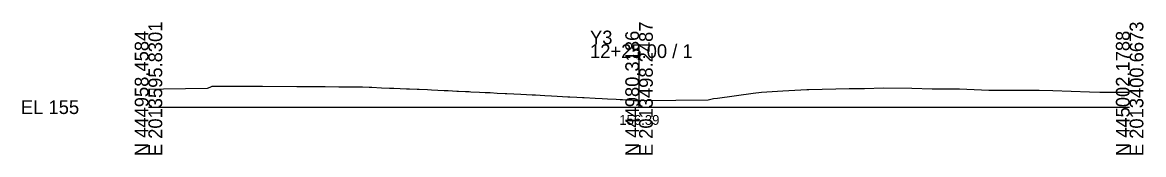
# Model space of a CAD drawing. Extents: x -26 to 203, y -10 to 5017.
# Drawn here: x -25.7 to 202.8, y 4490.3 to 4517.3 of the extents above; entities that cross this region are included whole.
import ezdxf

# ---------------------------------------------------------------- set-up
doc = ezdxf.new("R2010")
doc.units = 0
for name, color, linetype in [('Default', 7, 'Continuous'), ('Exist Cross Section Cell', 7, 'Continuous'), ('Exist XS Center Line Elevation Label', 7, 'Continuous'), ('Exist XS Ground Line', 7, 'Continuous')]:
    doc.layers.add(name, color=color, linetype=linetype)

msp = doc.modelspace()

# ---------------------------------------------------------------- linework, layer by layer
at = {"layer": 'Exist Cross Section Cell'}
for p, q in [((100, 4500), (100, 4512.84)), ((0, 4500), (100, 4500)), ((100, 4500), (200, 4500))]:
    msp.add_line(p, q, dxfattribs=at)
at = {"layer": 'Exist XS Ground Line'}
msp.add_lwpolyline([(0, 4503.69), (3.05, 4503.76), (12.01, 4503.86), (12.61, 4504.1), (12.99, 4504.26), (19.07, 4504.28), (19.62, 4504.28), (20.28, 4504.28), (21.07, 4504.27), (22.03, 4504.27), (23.24, 4504.26), (30.25, 4504.2), (31.85, 4504.2), (33.74, 4504.19), (36.02, 4504.19), (38.79, 4504.18), (42.3, 4504.17), (43.11, 4504.17), (43.66, 4504.15), (44.96, 4504.1), (45.5, 4504.07), (47.48, 4503.98), (49.12, 4503.91), (50.03, 4503.87), (52.58, 4503.76), (53.18, 4503.74), (54.8, 4503.67), (55.16, 4503.65), (56.89, 4503.58), (57.72, 4503.54), (58.98, 4503.48), (60.29, 4503.41), (61.08, 4503.38), (62.85, 4503.29), (63.17, 4503.28), (64.59, 4503.21), (65.34, 4503.18), (65.68, 4503.16), (67.46, 4503.08), (68.61, 4503.02), (69.12, 4503), (69.63, 4502.97), (71.09, 4502.89), (72.73, 4502.81), (73.08, 4502.79), (75.91, 4502.64), (78.21, 4502.53), (78.88, 4502.49), (80.77, 4502.4), (82.18, 4502.32), (83.32, 4502.26), (85.49, 4502.14), (85.9, 4502.12), (87.3, 4502.04), (88.46, 4501.98), (88.8, 4501.96), (91.03, 4501.84), (92.45, 4501.77), (93.58, 4501.71), (95.36, 4501.61), (96.13, 4501.57), (96.63, 4501.54), (97.4, 4501.5), (98.71, 4501.43), (99.08, 4501.39), (100, 4501.39), (107.47, 4501.43), (114.07, 4501.52), (115.18, 4501.74), (116, 4501.84), (123.29, 4502.89), (124.98, 4503.04), (129.32, 4503.36), (134.17, 4503.59), (134.6, 4503.59), (142.82, 4503.79), (145.96, 4503.83), (149.81, 4503.92), (155.61, 4503.89), (159.73, 4503.72), (165.3, 4503.72), (171.29, 4503.46), (180.74, 4503.49), (181.54, 4503.5), (184.32, 4503.39), (191.79, 4503.13), (193.95, 4503.04), (200, 4503.05)], dxfattribs=at)

# ---------------------------------------------------------------- texts
at = {"layer": 'Default'}
msp.add_text('-', height=0.0001, dxfattribs=at).set_placement((0, 4500))
at = {"layer": 'Exist Cross Section Cell'}
for s, p in [('E 2013595.8301', (2.8, 4490)), ('E 2013498.2487', (102.8, 4490)), ('E 2013400.6673', (202.8, 4490)), ('N 444958.4584', (0, 4490)), ('N 444980.3186', (100, 4490)), ('N 445002.1788', (200, 4490))]:
    msp.add_text(s, height=2.8, rotation=90, dxfattribs=at).set_placement(p)
for s, p in [('Y3', (90, 4512.84)), ('12+25.00 / 1', (90, 4510.04)), ('EL 155', (-26, 4498.6))]:
    msp.add_text(s, height=2.8, dxfattribs=at).set_placement(p)
at = {"layer": 'Exist XS Center Line Elevation Label'}
msp.add_text('156.39', height=2, dxfattribs=at).set_placement((95.97, 4496.39))

doc.saveas('drawing.dxf')
